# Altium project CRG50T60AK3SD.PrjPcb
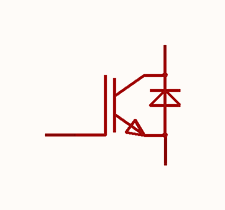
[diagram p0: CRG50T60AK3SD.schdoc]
1 sheet, 1 parts. Net scope: global (net labels, ports and power ports of the same name join across sheets).

## Sheet CRG50T60AK3SD.schdoc
size 127 x 101 mm

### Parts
Q?  crg50t60ak3sd  [TO-247-3_L15.9-W5.0-P5.44-L]  (value not drawn)

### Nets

Not connected (* = marked no-connect by the designer): Q? 1(G) 2(C) 3(E)

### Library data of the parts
Q? = crg50t60ak3sd: IGBT类型:FS(场截止);耗散功率(Pd):416W;集射极击穿电压(Vces):650V;集电极电流(Ic):50A;; Manufacturer: CRMICRO(华润微); AddInBom: yes; ModelId: 06d11a66e67643458860efec572770e6; ModelTransform: 625.983,196.85,0,0,0,0,0,5.906,-196.85; Pd - Power Dissipation: 416W; Collector-Emitter Breakdown Voltage (Vces): 650V; Current - Collector(Ic): 50A; Current - Collector Pulsed (Icm): 150A; Vce Saturation(VCE(sat)): 2.25V@50A,15V; Gate-Emitter Threshold Voltage (Vge(th)@Ic): 4V@1mA; Gate Charge(Qg): 303nC@15V; Input Capacitance(Cies): 7.719nF@30V; Output Capacitance(Coes): 189pF; Reverse Transfer Capacitance (Cres): 123pF; Td(on): 117ns; Td(off): 316ns; Turn-On Energy (Eon): 3.18mJ; Switching Energy(Eoff): 1.54mJ; Reverse Recovery Time(trr): 54ns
